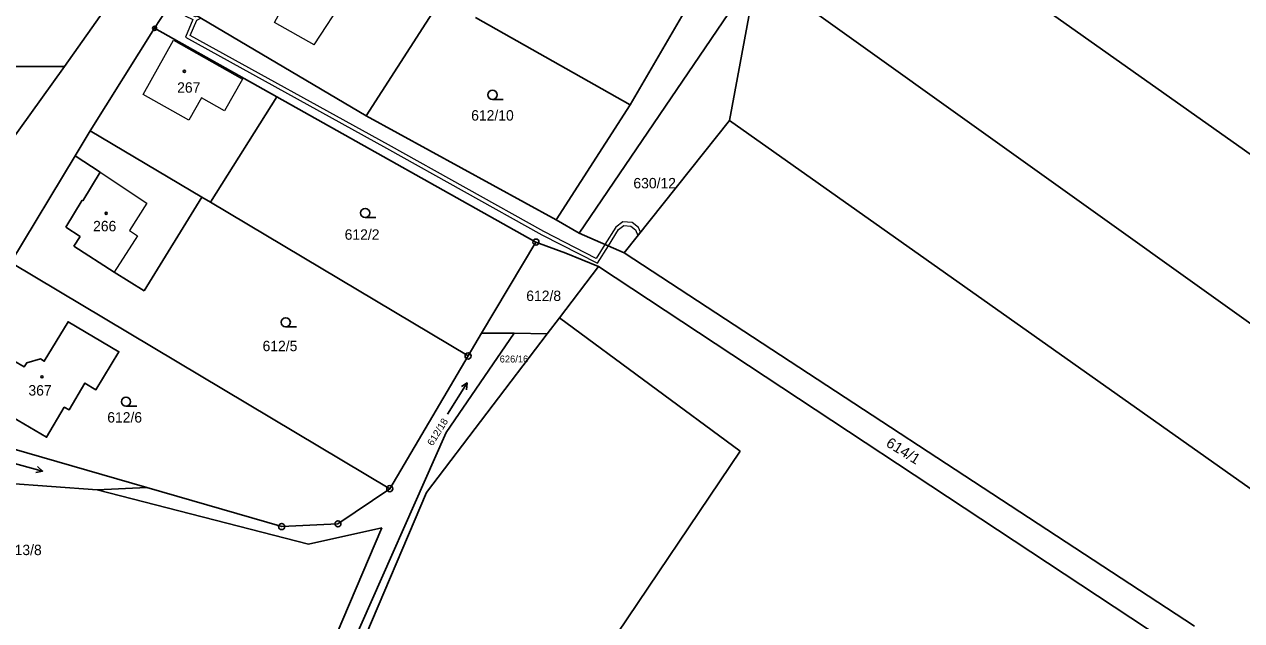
# Model space of a CAD drawing. Extents: x -694609 to -690140, y -1033292 to -1029794.
# Drawn here: x -692303.2 to -692104.2, y -1031550.7 to -1031453.2 of the extents above; entities that cross this region are included whole.
import ezdxf
from ezdxf.enums import TextEntityAlignment as Align

# ---------------------------------------------------------------- set-up
doc = ezdxf.new("R2010")
doc.units = 0
doc.header["$LTSCALE"] = 0.68
for name, color, linetype, lineweight in [('1', 7, 'Continuous', 25), ('13', 7, 'Continuous', 13), ('3', 7, 'Continuous', 25), ('4', 7, 'Continuous', 13), ('5', 7, 'Continuous', 25), ('8', 7, 'Continuous', 25)]:
    doc.layers.add(name, color=color, linetype=linetype, lineweight=lineweight)
doc.layers.add('2', color=7, linetype='Continuous')

msp = doc.modelspace()

# ---------------------------------------------------------------- linework, layer by layer
at = {"layer": '1'}
for p, q in [((-692170.59, -1031426.47), (-691908.31, -1031612.42)), ((-692183.39, -1031444.54), (-692212.51, -1031487.4)), ((-692204.16, -1031466.42), (-692191.66, -1031444.95)), ((-692183.39, -1031444.54), (-692187.96, -1031468.97)), ((-692183.39, -1031444.54), (-691926.83, -1031628.02)), ((-692247.34, -1031468.19), (-692235, -1031449.01)), ((-692289.29, -1031449.73), (-692296.63, -1031460.11)), ((-692279.13, -1031449.64), (-692281.9, -1031453.89)), ((-692247.34, -1031468.19), (-692276.65, -1031450.88)), ((-692204.16, -1031466.42), (-692229.48, -1031452.13)), ((-692292.43, -1031470.66), (-692281.9, -1031453.89)), ((-692261.95, -1031465.09), (-692281.9, -1031453.89)), ((-692296.63, -1031460.11), (-692321.65, -1031460.14)), ((-692296.63, -1031460.11), (-692310.42, -1031479.32)), ((-692261.95, -1031465.09), (-692272.74, -1031482.34)), ((-692219.59, -1031488.85), (-692261.95, -1031465.09)), ((-692216.28, -1031485.21), (-692204.16, -1031466.42)), ((-692216.28, -1031485.21), (-692247.34, -1031468.19)), ((-692187.96, -1031468.97), (-692205.16, -1031490.59)), ((-692187.96, -1031468.97), (-691943.57, -1031641.81)), ((-692294.9, -1031474.76), (-692292.43, -1031470.66)), ((-692292.43, -1031470.66), (-692274.17, -1031481.49)), ((-692305.4, -1031492.16), (-692294.9, -1031474.76)), ((-692290.81, -1031477.39), (-692294.9, -1031474.76)), ((-692293.63, -1031482.08), (-692290.81, -1031477.39)), ((-692296.39, -1031486.41), (-692293.73, -1031482.01)), ((-692293.73, -1031482.01), (-692293.63, -1031482.08)), ((-692283.59, -1031496.81), (-692274.17, -1031481.49)), ((-692274.17, -1031481.49), (-692272.74, -1031482.34)), ((-692272.74, -1031482.34), (-692230.66, -1031507.46)), ((-692212.51, -1031487.4), (-692216.28, -1031485.21)), ((-692296.39, -1031486.41), (-692294.08, -1031487.9)), ((-692295.1, -1031489.49), (-692294.08, -1031487.9)), ((-692228.45, -1031503.75), (-692219.59, -1031488.85)), ((-692219.59, -1031488.85), (-692214.68, -1031490.67)), ((-692205.16, -1031490.59), (-692212.51, -1031487.4)), ((-692288.5, -1031493.74), (-692295.1, -1031489.49)), ((-692214.68, -1031490.67), (-692209.35, -1031492.82)), ((-692205.16, -1031490.59), (-692111.95, -1031551.64)), ((-692243.47, -1031529.16), (-692305.4, -1031492.16)), ((-692209.35, -1031492.82), (-692215.73, -1031501.21)), ((-692209.35, -1031492.82), (-692116.89, -1031553.87)), ((-692288.5, -1031493.74), (-692283.59, -1031496.81)), ((-692215.73, -1031501.21), (-692217.74, -1031503.85)), ((-692186.22, -1031523.03), (-692215.73, -1031501.21)), ((-692217.74, -1031503.85), (-692237.48, -1031529.76)), ((-692234.23, -1031519.96), (-692223.15, -1031503.75)), ((-692230.66, -1031507.46), (-692228.45, -1031503.75)), ((-692223.15, -1031503.75), (-692228.45, -1031503.75)), ((-692217.74, -1031503.85), (-692223.15, -1031503.75)), ((-692230.66, -1031507.46), (-692243.47, -1031529.16)), ((-692321.02, -1031518), (-692283.17, -1031528.96)), ((-692234.23, -1031519.96), (-692271.28, -1031603.49)), ((-692208.18, -1031555.62), (-692186.22, -1031523.03)), ((-692291.29, -1031529.36), (-692306.24, -1031528.23)), ((-692291.29, -1031529.36), (-692283.17, -1031528.96)), ((-692283.17, -1031528.96), (-692261.13, -1031535.34)), ((-692256.74, -1031538.25), (-692291.29, -1031529.36)), ((-692237.48, -1031529.76), (-692275.6, -1031619.54)), ((-692251.94, -1031534.9), (-692243.47, -1031529.16)), ((-692261.13, -1031535.34), (-692251.94, -1031534.9)), ((-692273.27, -1031602.4), (-692244.77, -1031535.57)), ((-692244.77, -1031535.57), (-692256.74, -1031538.25))]:
    msp.add_line(p, q, dxfattribs=at)
msp.add_lwpolyline([(-692306.6, -1031507.25), (-692303.23, -1031509.25), (-692302.79, -1031508.59), (-692300.57, -1031507.94), (-692299.93, -1031508.31), (-692296.03, -1031501.86), (-692287.74, -1031506.77), (-692291.49, -1031512.97), (-692293.3, -1031511.9), (-692295.89, -1031516.29), (-692296.67, -1031515.84), (-692299.56, -1031520.75), (-692310.71, -1031514.2)], close=True, dxfattribs=at)
at = {"layer": '13'}
for points in [[(-692276.91, -1031451.85), (-692275.63, -1031452.47), (-692276.84, -1031455.35), (-692244, -1031473.47), (-692218.59, -1031487.63), (-692209.5, -1031492.29), (-692207.74, -1031489.47), (-692208.3, -1031489.23), (-692209.72, -1031491.51), (-692218.31, -1031487.11), (-692243.7, -1031472.95), (-692276.08, -1031455.07), (-692275.02, -1031452.56), (-692274.33, -1031452.25), (-692274.94, -1031451.89), (-692275.23, -1031452), (-692276.51, -1031451.38), (-692277.05, -1031450.68), (-692277.62, -1031450.4), (-692277.84, -1031450.61)], [(-692205.38, -1031485.52), (-692206.53, -1031486.38), (-692208.3, -1031489.23), (-692207.74, -1031489.47), (-692206.08, -1031486.8), (-692205.2, -1031486.14), (-692204.09, -1031486.23), (-692203.3, -1031486.82), (-692202.9, -1031487.75), (-692202.48, -1031487.22), (-692202.82, -1031486.44), (-692203.87, -1031485.65)]]:
    msp.add_lwpolyline(points, close=True, dxfattribs=at)
at = {"layer": '3'}
for p, q in [((-692226.673, -1031465.52), (-692224.923, -1031465.52)), ((-692247.483, -1031484.83), (-692245.733, -1031484.83)), ((-692260.463, -1031502.7), (-692258.713, -1031502.7)), ((-692230.824, -1031511.876), (-692230.916, -1031512.97)), ((-692286.573, -1031515.68), (-692284.823, -1031515.68)), ((-692300.218, -1031526.279), (-692301.292, -1031526.511))]:
    msp.add_line(p, q, dxfattribs=at)
for points in [[(-692234.003, -1031516.964), (-692230.824, -1031511.876), (-692231.767, -1031512.439)], [(-692306.013, -1031524.726), (-692300.218, -1031526.279), (-692301.032, -1031525.542)]]:
    msp.add_lwpolyline(points, dxfattribs=at)
for centre in [(-692226.6729, -1031464.7698), (-692247.4829, -1031484.0798), (-692260.4629, -1031501.9498), (-692286.5729, -1031514.9298)]:
    msp.add_circle(centre, 0.75, dxfattribs=at)
at = {"layer": '4'}
for p, q in [((-692255.81, -1031456.59), (-692249.23, -1031446.44)), ((-692290.81, -1031477.39), (-692283.17, -1031482.48)), ((-692283.17, -1031482.48), (-692286.03, -1031486.94)), ((-692286.03, -1031486.94), (-692284.69, -1031487.81)), ((-692284.69, -1031487.81), (-692288.5, -1031493.74))]:
    msp.add_line(p, q, dxfattribs=at)
for points in [[(-692255.81, -1031456.59), (-692262.31, -1031452.94), (-692261.3, -1031451.15), (-692262.48, -1031450.49), (-692260.14, -1031446.32)], [(-692276.29, -1031468.91), (-692283.79, -1031464.7), (-692278.81, -1031455.85), (-692267.56, -1031462.18)], [(-692267.56, -1031462.18), (-692270.48, -1031467.36), (-692274.23, -1031465.25), (-692276.29, -1031468.91)]]:
    msp.add_lwpolyline(points, dxfattribs=at)
at = {"layer": '5'}
for centre in [(-692277.0368, -1031460.9292), (-692289.8168, -1031484.1292), (-692300.2968, -1031510.8692)]:
    msp.add_circle(centre, 0.175, dxfattribs=at)
at = {"layer": '8'}
for centre, radius in [((-692281.9, -1031453.8899), 0.335), ((-692281.9, -1031453.8899), 0.0203), ((-692219.59, -1031488.8499), 0.5), ((-692219.59, -1031488.8499), 0.0303), ((-692230.66, -1031507.4599), 0.5), ((-692230.66, -1031507.4599), 0.0303), ((-692243.47, -1031529.1599), 0.5), ((-692243.47, -1031529.1599), 0.0303), ((-692261.13, -1031535.3399), 0.5), ((-692251.94, -1031534.8999), 0.5), ((-692251.94, -1031534.8999), 0.0303), ((-692261.13, -1031535.3399), 0.0303)]:
    msp.add_circle(centre, radius, dxfattribs=at)

# ---------------------------------------------------------------- texts
at = {"layer": '2'}
for s, height, p in [('267', 1.7, (-692276.319, -1031464.415)), ('612/10', 1.7, (-692226.68, -1031468.975)), ('630/12', 1.7, (-692200.17, -1031480.055)), ('266', 1.7, (-692290.059, -1031487.075)), ('612/2', 1.7, (-692247.99, -1031488.455)), ('612/8', 1.7, (-692218.31, -1031498.475)), ('612/5', 1.7, (-692261.41, -1031506.675)), ('626/16', 1.14, (-692223.169, -1031508.525)), ('367', 1.7, (-692300.629, -1031513.925)), ('612/6', 1.7, (-692286.79, -1031518.345))]:
    msp.add_text(s, height=height, dxfattribs=at).set_placement(p, align=Align.CENTER)
at = {"layer": '2', "width": 1.05}
for s, height, rotation, p in [('612/18', 1.14, 58, (-692235.1722, -1031520.1771)), ('614/1', 1.7, 328, (-692159.9759, -1031523.6829))]:
    msp.add_text(s, height=height, rotation=rotation, dxfattribs=at).set_placement(p, align=Align.CENTER)
at = {"layer": '2'}
msp.add_text('613/8', height=1.7, dxfattribs=at).set_placement((-692306.04, -1031540.015))

doc.saveas('drawing.dxf')
